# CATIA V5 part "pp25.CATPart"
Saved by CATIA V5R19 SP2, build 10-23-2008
Part number: pp25
Bounding box of the stored display mesh (mm): x -18 to 18, y -428.389 to -211.611, z -68 to -34.575
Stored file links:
  D:\thinkmotion-MPB\Dropbox\Pack 1 sylvain\jlicbarski\thk2\pp25.CATPart
  D:\thinkmotion-MPB\Dropbox\Pack 1 sylvain\jlicbarski\thk2\Brasmeca.CATProduct
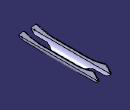
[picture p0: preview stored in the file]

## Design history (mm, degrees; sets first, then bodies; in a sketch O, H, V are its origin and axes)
External parameters (linked from other documents)
  External.Length.3 = 36 mm
  External.Length.5 = 17.604 mm
  External.Length.2 = 18 mm
  External.Length.1 = 16 mm
  External.Length.4 = 32 mm
  External.Length.7 = 8.799 mm
  External.Length.8 = 6.95 mm
  External.Length.6 = 1.601 mm
  External.Length.9 = 1.745 mm
AxisSystem1: origin (0, -320, 0), X (1, 0, 0), Y (0, 1, 0), Z (0, 0, 1)
Set1
  Plane1: linked copy from another document
  Line1: linked copy from another document
  Sketch1, origin (5, 0, 0), H (0, 1, 0), V (0, 0, 1), geometry linked from another document
Body1 (main body)
  Sketch2 on Plane1, origin (0, -210, 0), H (-1, 0, 0), V (0, 0, 1)
    point P1 (16, -50)
    arc A1 centre (0, -50) radius 18 from (-18, -50) to (18, -50) ccw
    point P4 (-16, -50)
    line L1 (18, -50) -> (18, -32.396)
    line L2 (16, -50) -> (16, -32.396)
    line L3 (-16, -50) -> (-16, -32.396)
    line L4 (-18, -50) -> (-18, -32.396)
    line L5 (-18, -32.396) -> (-16, -32.396)
    line L6 (16, -32.396) -> (18, -32.396)
    arc A2 centre (0, -50) radius 16 from (-16, -50) to (16, -50) ccw
    point P10 (-16, -50)
    point P11 (16, -50)
    reference projected point E1 (0, -50) from Line1
    reference projected point E2 (0, -50) from Line1
    length L1 = 17.604 {= External.Length.5}
    length L2 = 17.604 {= External.Length.5}
    length L3 = 17.604 {= External.Length.5}
    length L4 = 17.604 {= External.Length.5}
    radius A1 = 18 {= External.Length.3 /2}
    radius A2 = 16 {= External.Length.4 /2}
    distance A1 E1 = 18 {= External.Length.2}
    distance A2 E2 = 16 {= External.Length.1}
    coincidence: P1 P11, P4 P10
  Pad1: profile Sketch2, direction (0, -1, 0), length 220
  Sketch3 on face of Pad1 from Sketch2.L4, origin (18, 0, 0), H (0, 1, 0), V (0, 0, 1)
    line L1 (-226.5998, -58.799) -> (-250.117, -58.799)
    line L2 (-276.3565, -43.05) -> (-288.7604, -43.05)
    reference projected line E1 (-210, -50) -> (-430, -50) from edge [face of Pad1 from Sketch2.L4 | face of Pad1 from Sketch2.A1]
    reference projected line E2 (-210, -50) -> (-430, -50) from edge [face of Pad1 from Sketch2.L4 | face of Pad1 from Sketch2.A1]
    line L3 (-214.0595, -54.2225) -> (-212.6025, -52.4761)
    line L4 (-212.4426, -47.1518) -> (-222.3023, -35.9014)
    arc A1 centre (-215.9159, -49.712) radius 4.3149 from (-212.6025, -52.4761) to (-212.4426, -47.1518) ccw
    reference projected line E3 (-210, -32.396) -> (-210, -50) from edge [face of Pad1 from Sketch2.L4 | start face of Pad1]
    arc A2 centre (-276.3565, 100.5453) radius 143.5953 from (-228.8911, -34.9783) to (-276.3565, -43.05) cw
    point P9 (-225.5732, -33.7702)
    line L5 (-222.3023, -35.9014) -> (-222.541, -35.7459)
    arc A3 centre (-226.4962, -41.8163) radius 7.2452 from (-228.8911, -34.9783) to (-222.541, -35.7459) cw
    line L6 (-226.5998, -58.799) -> (-219.3866, -57.3368)
    line L7 (-219.3866, -57.3368) -> (-214.0595, -54.2225)
    line L8 (-250.117, -58.799) -> (-257.363, -58.799)
    line L9 (-257.363, -58.799) -> (-280.1427, -66.2897)
    line L10 (-261.6792, -77.7953) -> (-228.8911, -80.2929)
    line L11 (-378.3208, -77.7953) -> (-411.1089, -80.2929)
    line L12 (-382.637, -58.799) -> (-359.8573, -66.2897)
    line L13 (-389.883, -58.799) -> (-382.637, -58.799)
    line L14 (-413.4002, -58.799) -> (-389.883, -58.799)
    line L15 (-413.4002, -58.799) -> (-420.6134, -57.3368)
    line L16 (-420.6134, -57.3368) -> (-425.9405, -54.2225)
    arc A4 centre (-424.0841, -49.712) radius 4.3149 from (-427.3975, -52.4761) to (-427.5574, -47.1518) cw
    line L17 (-425.9405, -54.2225) -> (-427.3975, -52.4761)
    line L18 (-427.5574, -47.1518) -> (-417.6977, -35.9014)
    arc A5 centre (-413.5038, -41.8163) radius 7.2452 from (-411.1089, -34.9783) to (-417.459, -35.7459) ccw
    arc A6 centre (-363.6435, 100.5453) radius 143.5953 from (-411.1089, -34.9783) to (-363.6435, -43.05) ccw
    line L19 (-363.6435, -43.05) -> (-351.2396, -43.05)
    line L20 (-288.7604, -43.05) -> (-351.2396, -43.05)
    line L21 (-190.1221, -41.8163) -> (-214.9736, -19.6546)
    line L22 (-214.9736, -19.6546) -> (-442.2939, -21.5196)
    line L23 (-442.2939, -21.5196) -> (-457.2048, -59.5964)
    arc A7 centre (-433.6518, -68.8198) radius 25.2946 from (-457.2048, -59.5964) to (-411.1089, -80.2929) ccw
    line L24 (-228.8911, -80.2929) -> (-186.3149, -80.2929)
    line L25 (-186.3149, -80.2929) -> (-190.1221, -41.8163)
    line L26 (-280.1427, -66.2897) -> (-305.9857, -74.4203)
    line L27 (-305.9857, -74.4203) -> (-261.6792, -77.7953)
    line L28 (-359.8573, -66.2897) -> (-334.7625, -74.4773)
    line L29 (-334.7625, -74.4773) -> (-378.3208, -77.7953)
    distance L1 E1 = 8.799 {= External.Length.7}
    distance L2 E2 = 6.95 {= External.Length.8}
    distance A1 E3 = 1.601 {= External.Length.6}
    distance L19 E2 = 6.95
    distance L14 E1 = 8.799
    coincidence: L5 P9
  Pocket1: profile Sketch3, direction (-1, 0, 0), length 220
  Pocket2: profile Sketch1, direction (1, 0, 0), length 220
  Pocket3: profile Sketch1, direction (-1, 0, 0), length 220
